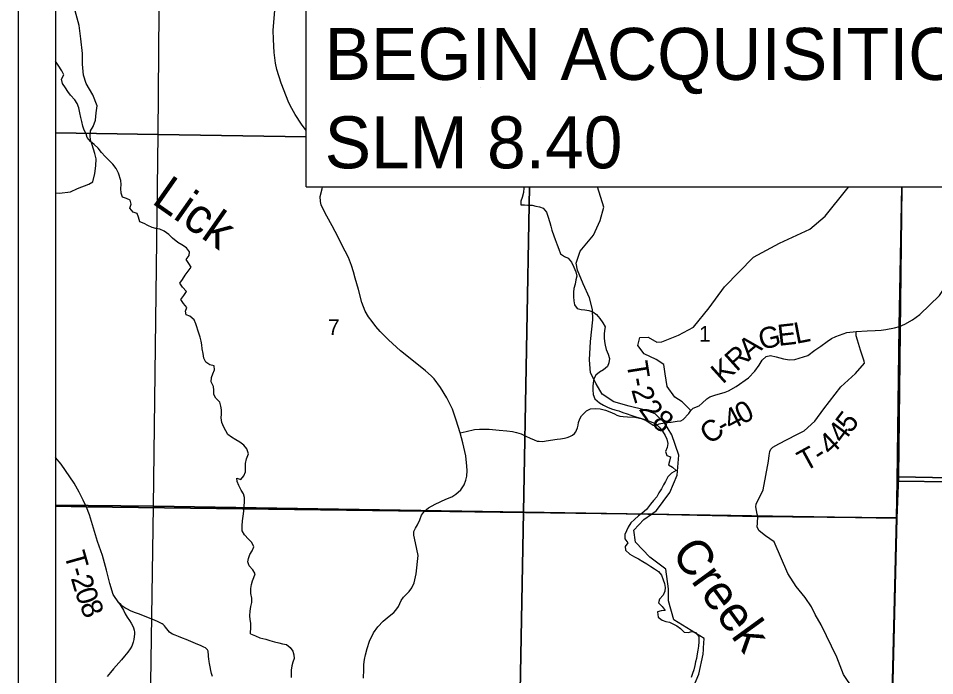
# Model space of a CAD drawing. Extents: x -19 to 40.8, y -1.8 to 26.1.
# Drawn here: x 2 to 4.466, y 15.443 to 17.213 of the extents above; entities that cross this region are included whole.
import ezdxf

# ---------------------------------------------------------------- set-up
doc = ezdxf.new("R2010")
doc.units = 0
for name, color, linetype in [('Default', 7, 'Continuous'), ('GM_X_Corporation', 7, 'Continuous'), ('GM_X_County_Road_Text', 7, 'Continuous'), ('GM_X_Minor_River', 7, 'Continuous'), ('GM_X_Rail_Line', 7, 'Continuous'), ('GM_X_Section', 7, 'Continuous'), ('GM_X_Section_Text', 7, 'Continuous'), ('GM_X_State_Route', 7, 'Continuous'), ('GM_X_Township_Road_Text', 7, 'Continuous'), ('RW_P_Text', 7, 'Continuous'), ('SH_Data', 7, 'Continuous'), ('SH_Text', 7, 'Continuous')]:
    doc.layers.add(name, color=color, linetype=linetype)

msp = doc.modelspace()

# ---------------------------------------------------------------- linework, layer by layer
at = {"layer": 'Default'}
for points in [[(2.1, 17.9061), (2.1, 16.9049), (2.3762, 16.9005), (2.3844, 17.899)], [(2.1, 16.9049), (2.1, 15.9023), (2.3634, 15.8992), (2.3762, 16.9005)], [(2.1, 15.9023), (2.1, 14.6614), (2.3446, 14.653), (2.3634, 15.8992)]]:
    msp.add_lwpolyline(points, close=True, dxfattribs=at)
at = {"layer": 'GM_X_Corporation'}
for points in [[(4.322, 16.3734), (4.3339, 16.3753), (4.3577, 16.3797), (4.3706, 16.3834), (4.3855, 16.3895), (4.4057, 16.4008), (4.4252, 16.4157), (4.4782, 16.4668), (4.5425, 16.5606), (4.5843, 16.6158), (4.5904, 16.6203), (4.6059, 16.6276), (4.6175, 16.6345), (4.6319, 16.6465), (4.6514, 16.663), (4.6648, 16.6758), (4.6846, 16.69), (4.6854, 16.6904)], [(3.1892, 16.0973), (3.2052, 16.1003), (3.2275, 16.1057), (3.2405, 16.1067), (3.2671, 16.1064), (3.2942, 16.1044), (3.3141, 16.1027), (3.3292, 16.1006), (3.3402, 16.098), (3.3534, 16.0938), (3.3655, 16.0884), (3.3772, 16.083), (3.3879, 16.0783), (3.396, 16.0749), (3.4017, 16.0743), (3.4116, 16.0736), (3.4206, 16.075), (3.4501, 16.0803), (3.4589, 16.0812), (3.4697, 16.0823), (3.4768, 16.084), (3.484, 16.0867), (3.4914, 16.0908), (3.4965, 16.0952), (3.4999, 16.1), (3.5017, 16.1041), (3.5042, 16.1105), (3.5059, 16.1173), (3.5074, 16.1249), (3.5105, 16.135), (3.5156, 16.1428), (3.5233, 16.1509), (3.5287, 16.1566), (3.5396, 16.1618), (3.5538, 16.1629), (3.5652, 16.1613), (3.5798, 16.1579), (3.5919, 16.1539), (3.6038, 16.1483), (3.6105, 16.1445), (3.6181, 16.1422), (3.6278, 16.1409), (3.639, 16.14), (3.6587, 16.1395), (3.6754, 16.1357), (3.6891, 16.1303), (3.7085, 16.1175), (3.7152, 16.1166), (3.7246, 16.1209), (3.7386, 16.1236), (3.7566, 16.1261), (3.773, 16.128), (3.7823, 16.1294), (3.789, 16.1324), (3.8043, 16.1493), (3.8096, 16.1568), (3.8156, 16.1631), (3.8317, 16.1695), (3.8399, 16.1769), (3.8529, 16.1885), (3.8604, 16.1936), (3.8766, 16.1993), (3.8928, 16.2034), (3.9018, 16.2063), (3.9112, 16.2103), (3.9318, 16.2221), (3.9647, 16.2453), (3.9817, 16.2631), (3.9934, 16.2791), (4.001, 16.293), (4.0125, 16.3029), (4.0235, 16.3055), (4.0392, 16.3018), (4.0591, 16.2958), (4.0753, 16.2935), (4.0892, 16.2948), (4.1241, 16.3052), (4.1428, 16.3193), (4.1592, 16.3304), (4.1761, 16.3424), (4.1877, 16.3508), (4.2, 16.3566), (4.2288, 16.3667), (4.2544, 16.3699), (4.2838, 16.3713), (4.3054, 16.3724), (4.322, 16.3734)]]:
    msp.add_lwpolyline(points, dxfattribs=at)
at = {"layer": 'GM_X_Rail_Line'}
for points in [[(2.7742, 16.9108), (2.7623, 16.9277), (2.7447, 16.9536), (2.7356, 16.9701), (2.728, 16.9852), (2.7071, 17.038), (2.6958, 17.0752), (2.6919, 17.0924), (2.6882, 17.1209), (2.6864, 17.1555), (2.6861, 17.1808), (2.6885, 17.212), (2.6932, 17.2685), (2.6965, 17.3146), (2.6969, 17.3334)], [(2.844, 16.6542), (2.8301, 16.6799), (2.8206, 16.6987), (2.8148, 16.7112), (2.813, 16.7195), (2.8123, 16.7331), (2.8175, 16.7541), (2.8187, 16.7589)], [(3.1892, 16.0973), (3.1785, 16.131), (3.1679, 16.1604), (3.153, 16.1915), (3.1362, 16.2193), (3.1192, 16.2419), (3.1106, 16.2504), (3.0954, 16.2637), (3.0635, 16.2895), (3.028, 16.3174), (2.9964, 16.3472), (2.9736, 16.3694), (2.962, 16.3836), (2.9518, 16.3964), (2.9421, 16.4096), (2.9332, 16.4248), (2.9244, 16.4476), (2.915, 16.4826), (2.9066, 16.5135), (2.9017, 16.5308), (2.8962, 16.5472), (2.8886, 16.5687), (2.8794, 16.5862), (2.8522, 16.6391), (2.844, 16.6542)], [(2.9285, 15.4367), (2.9292, 15.4595), (2.9299, 15.4732), (2.9315, 15.4867), (2.934, 15.4996), (2.9388, 15.5164), (2.9452, 15.5364), (2.9559, 15.5585), (2.9675, 15.5742), (2.9813, 15.5895), (2.9925, 15.5993), (3.002, 15.6065), (3.0102, 15.6135), (3.0161, 15.6197), (3.0226, 15.6298), (3.03, 15.6452), (3.0365, 15.6544), (3.0514, 15.6695), (3.0588, 15.6792), (3.0652, 15.693), (3.0703, 15.7174), (3.0755, 15.767), (3.0686, 15.8008), (3.0646, 15.8215), (3.0646, 15.8315), (3.0683, 15.8404), (3.0743, 15.8496), (3.0807, 15.8631), (3.0852, 15.8751), (3.0928, 15.8856), (3.1035, 15.8948), (3.1213, 15.9052), (3.1507, 15.9186), (3.1661, 15.9247), (3.1772, 15.9318), (3.1905, 15.9439), (3.1997, 15.9569), (3.2043, 15.9695), (3.2066, 15.9804), (3.2074, 15.9953), (3.2069, 16.0076), (3.2043, 16.0346), (3.1964, 16.0704), (3.1892, 16.0973)]]:
    msp.add_lwpolyline(points, dxfattribs=at)
at = {"layer": 'GM_X_Section'}
msp.add_line((3.243, 17.0276), (3.243, 17.0276), dxfattribs=at)
for points in [[(2.4048, 16.6307), (2.3925, 16.6397), (2.3806, 16.6452), (2.3703, 16.647), (2.36, 16.6502), (2.3489, 16.6554), (2.3385, 16.6606), (2.3271, 16.665), (2.3235, 16.6779), (2.3195, 16.6877), (2.3092, 16.6914), (2.2999, 16.7015), (2.304, 16.713), (2.3012, 16.7236), (2.2908, 16.7276), (2.2801, 16.7313), (2.2766, 16.7419), (2.276, 16.7552), (2.2766, 16.7651), (2.2754, 16.7761), (2.2698, 16.7957), (2.2631, 16.8082), (2.2546, 16.8203), (2.2446, 16.8304), (2.2341, 16.8409), (2.2241, 16.8518), (2.2144, 16.863), (2.204, 16.8732), (2.194, 16.881), (2.1855, 16.8919), (2.1823, 16.9018), (2.1773, 16.9116), (2.1733, 16.9222), (2.1705, 16.9351), (2.1681, 16.9457), (2.1656, 16.9586), (2.1628, 16.9715), (2.1584, 16.9832), (2.1522, 16.9934), (2.1406, 17.0061), (2.1329, 17.0163), (2.127, 17.0261), (2.1189, 17.037), (2.1164, 17.0495), (2.122, 17.0606), (2.1169, 17.0716), (2.1076, 17.0867), (2.1, 17.098)], [(3.3594, 16.7589), (3.3597, 16.7565), (3.3591, 16.7439), (3.3554, 16.7306), (3.3525, 16.7203), (3.3523, 16.7108), (3.3618, 16.7109), (3.3713, 16.7103), (3.3824, 16.7097), (3.3923, 16.7075), (3.4022, 16.7054), (3.4118, 16.7017), (3.4211, 16.6908), (3.425, 16.6806), (3.4298, 16.6628), (3.433, 16.653), (3.4358, 16.6427), (3.4409, 16.6272), (3.4441, 16.6174), (3.4496, 16.6034), (3.454, 16.5917), (3.4591, 16.5792), (3.4691, 16.5713), (3.479, 16.5673), (3.4883, 16.556), (3.495, 16.5428), (3.5001, 16.53), (3.5029, 16.519), (3.4996, 16.5087), (3.4979, 16.4976), (3.495, 16.4854), (3.494, 16.4759), (3.4938, 16.463), (3.4946, 16.4527), (3.4967, 16.4417), (3.5037, 16.4319), (3.5147, 16.4294), (3.5247, 16.4284), (3.5353, 16.4263), (3.546, 16.4223), (3.5557, 16.4155), (3.5645, 16.405), (3.5723, 16.393), (3.5789, 16.3824), (3.5772, 16.3725), (3.5765, 16.3626), (3.5767, 16.3524), (3.5776, 16.3429), (3.5788, 16.3326), (3.582, 16.3213), (3.5871, 16.3088), (3.5904, 16.297), (3.589, 16.2852), (3.5853, 16.2757), (3.5744, 16.2668), (3.5638, 16.2602), (3.5537, 16.2521), (3.5489, 16.2425), (3.5471, 16.2314)], [(2.6251, 15.5557), (2.6256, 15.5746), (2.6255, 15.5849), (2.6238, 15.5944), (2.6229, 15.6043), (2.6239, 15.6168), (2.626, 15.6294), (2.6282, 15.6404), (2.628, 15.6518), (2.6252, 15.664), (2.6254, 15.678), (2.6271, 15.6887), (2.63, 15.6983), (2.6333, 15.7078), (2.637, 15.7174), (2.6308, 15.7283), (2.6215, 15.7388), (2.6172, 15.7494), (2.6193, 15.7589), (2.623, 15.7692), (2.6289, 15.7796), (2.6334, 15.7899), (2.6286, 15.802), (2.619, 15.8106), (2.6082, 15.8223), (2.6027, 15.8332), (2.6022, 15.8465), (2.6035, 15.8598), (2.6049, 15.8724), (2.607, 15.8861), (2.6075, 15.899), (2.6085, 15.9124), (2.6087, 15.9226), (2.6059, 15.9329), (2.5993, 15.943), (2.5935, 15.9551), (2.5888, 15.9657), (2.5875, 15.9752), (2.5986, 15.9715), (2.6068, 15.9815), (2.6112, 15.9922), (2.6114, 16.0048), (2.6113, 16.0143), (2.6142, 16.0269), (2.6197, 16.0406), (2.6146, 16.0535), (2.6072, 16.0633), (2.5961, 16.0719), (2.585, 16.0785), (2.5738, 16.0856), (2.5638, 16.0927), (2.5533, 16.1119), (2.5474, 16.1244), (2.5461, 16.1377), (2.5471, 16.1472), (2.5466, 16.1586), (2.5453, 16.1689), (2.5425, 16.1791), (2.5317, 16.19), (2.5262, 16.1998), (2.5257, 16.2115), (2.5252, 16.2214), (2.5193, 16.2339), (2.5195, 16.246), (2.5232, 16.256), (2.5276, 16.2663), (2.5271, 16.2773), (2.5157, 16.2798), (2.5049, 16.2869), (2.4994, 16.2982), (2.497, 16.3107), (2.4949, 16.3229), (2.4936, 16.3339), (2.4916, 16.3441), (2.4892, 16.3547), (2.486, 16.3653), (2.4773, 16.3903), (2.4729, 16.4013), (2.4618, 16.4114), (2.4518, 16.4143), (2.4498, 16.4245), (2.4538, 16.4348), (2.4442, 16.4454), (2.4372, 16.4563), (2.445, 16.4663), (2.4521, 16.4774), (2.4417, 16.4894), (2.4347, 16.4996), (2.4418, 16.5096), (2.4492, 16.5215), (2.4571, 16.5318), (2.4646, 16.5426), (2.4591, 16.5524), (2.4517, 16.5637), (2.4599, 16.5748), (2.461, 16.5843), (2.4521, 16.5952), (2.4402, 16.6027), (2.4294, 16.6098), (2.4148, 16.6213), (2.4048, 16.6307)], [(3.5471, 16.2314), (3.5461, 16.2219), (3.5455, 16.2124), (3.5468, 16.1999), (3.5515, 16.1885), (3.5638, 16.1777), (3.5749, 16.1714), (3.5849, 16.1662), (3.5956, 16.1618), (3.6051, 16.1592), (3.6158, 16.1564), (3.6262, 16.1519), (3.638, 16.1479), (3.648, 16.1446), (3.6613, 16.1403), (3.6827, 16.1337), (3.6938, 16.1301), (3.7049, 16.126), (3.7145, 16.122), (3.7245, 16.1119), (3.733, 16.101), (3.7408, 16.0901), (3.7451, 16.0795), (3.7472, 16.0681), (3.7462, 16.0578), (3.7417, 16.0463), (3.7449, 16.0357), (3.7552, 16.0325), (3.752, 16.0203), (3.7495, 16.0107), (3.7602, 16.0048), (3.7698, 15.9954), (3.7577, 15.9888), (3.7476, 15.9784), (3.7409, 15.9661), (3.7361, 15.9566), (3.7302, 15.9458), (3.7234, 15.9358), (3.7183, 15.9248), (3.7093, 15.9144), (3.7007, 15.9047), (3.6898, 15.8901), (3.6785, 15.8809), (3.6687, 15.8735), (3.6578, 15.8638), (3.6484, 15.8542), (3.6406, 15.8431), (3.6366, 15.8331), (3.6321, 15.8228), (3.6319, 15.8118), (3.6397, 15.8009), (3.6326, 15.7913), (3.6338, 15.781), (3.6454, 15.7702), (3.6577, 15.7635), (3.6688, 15.7576), (3.6807, 15.7505), (3.6914, 15.7442), (3.7021, 15.7375), (3.7121, 15.7304), (3.7221, 15.7237), (3.7302, 15.7136), (3.7354, 15.7015), (3.7389, 15.6909), (3.7402, 15.6806), (3.7392, 15.6707), (3.7348, 15.6596), (3.725, 15.6489), (3.7225, 15.6393), (3.7325, 15.6296), (3.7407, 15.6187), (3.7293, 15.6177), (3.7194, 15.6153), (3.7215, 15.6005), (3.7319, 15.5927), (3.7418, 15.589), (3.7517, 15.5873), (3.7715, 15.5773)], [(3.7715, 15.5773), (3.7814, 15.5699), (3.7917, 15.5601), (3.802, 15.559), (3.8122, 15.5622), (3.8217, 15.5592), (3.8313, 15.5483), (3.8311, 15.5346), (3.83, 15.5228), (3.8282, 15.5114), (3.8268, 15.5015), (3.8246, 15.4897), (3.8224, 15.4802), (3.8202, 15.4703), (3.8173, 15.4592), (3.8136, 15.4486), (3.8102, 15.4383)], [(2.6251, 15.5557), (2.6384, 15.5505), (2.6502, 15.5449), (2.6662, 15.5412), (2.6765, 15.5382), (2.6891, 15.5345), (2.7005, 15.5316), (2.7104, 15.529), (2.7218, 15.5268), (2.7318, 15.5189), (2.7387, 15.5091), (2.7414, 15.4992), (2.7423, 15.4897), (2.7389, 15.4798), (2.736, 15.4699), (2.7342, 15.4581), (2.7344, 15.4384)]]:
    msp.add_lwpolyline(points, dxfattribs=at)
at = {"layer": 'GM_X_State_Route'}
for points in [[(4.3921, 17.8104), (4.3932, 17.8891), (4.4038, 18.6476), (4.4141, 19.3749), (4.4289, 20.4268), (4.4356, 20.9), (2.1, 20.9), (2.1, 15.8991), (2.1833, 15.8974), (3.0926, 15.8861), (3.7032, 15.8784), (3.9893, 15.872), (4.3628, 15.868), (4.3644, 15.9666), (4.3704, 16.384), (4.3769, 16.7589)], [(2.1, 16.7433), (2.1105, 16.7418), (2.1404, 16.7461), (2.1594, 16.755), (2.1894, 16.7662), (2.2006, 16.7729), (2.2057, 16.7948), (2.2083, 16.8162), (2.2098, 16.835), (2.2062, 16.8493), (2.1986, 16.8722), (2.1945, 16.8849), (2.1935, 16.8976), (2.1944, 16.91), (2.2013, 16.9215), (2.2078, 16.9387), (2.2093, 16.9581), (2.2123, 16.9776), (2.2001, 17.0071), (2.1823, 17.0377), (2.1757, 17.0596), (2.1731, 17.0891), (2.1726, 17.1182), (2.168, 17.1579), (2.1635, 17.194), (2.1533, 17.2333)], [(3.7386, 16.1236), (3.7135, 16.1479), (3.6837, 16.1587), (3.6433, 16.1684), (3.6025, 16.1804), (3.5713, 16.201), (3.5544, 16.2291), (3.5398, 16.2587), (3.5368, 16.2932), (3.5395, 16.3425), (3.5458, 16.4015), (3.5448, 16.4291), (3.5366, 16.4604), (3.5202, 16.4984), (3.5043, 16.5345), (3.5005, 16.5541), (3.5115, 16.5862), (3.5478, 16.6291), (3.5655, 16.6686), (3.5753, 16.7048), (3.5585, 16.7589)], [(3.7401, 16.256), (3.7364, 16.2806), (3.7158, 16.2948), (3.6842, 16.3096), (3.6665, 16.3325), (3.6723, 16.3538), (3.6943, 16.3548), (3.7183, 16.3411), (3.7312, 16.342), (3.7765, 16.3603), (3.8168, 16.3816), (3.8591, 16.4333), (3.9002, 16.4899), (3.9778, 16.5697), (4.0479, 16.6076), (4.1294, 16.6457), (4.1707, 16.6803), (4.2294, 16.7534), (4.2345, 16.7589)], [(4.3769, 16.7589), (4.3704, 16.384), (4.3644, 15.9666), (5.2419, 15.956), (5.3769, 15.9544), (5.3823, 15.9544), (5.3878, 15.9543), (5.57, 15.952), (6.2458, 15.936), (6.5861, 15.9329), (6.6409, 15.9314), (6.7023, 15.9297), (6.805, 15.9268), (6.9672, 15.9223), (6.993, 15.9217), (6.9993, 15.9207), (7.1288, 15.9169)], [(3.9882, 15.8783), (3.9844, 15.8977), (3.9855, 15.9053), (4.0038, 15.9433), (4.0187, 16.0204), (4.0204, 16.0356), (4.0216, 16.0469), (4.0244, 16.0526), (4.0299, 16.0581), (4.0466, 16.0676), (4.0691, 16.0787), (4.0946, 16.0921), (4.1148, 16.1025), (4.1428, 16.1284), (4.167, 16.1616), (4.2128, 16.221), (4.2527, 16.2571), (4.2771, 16.2848), (4.2756, 16.2899), (4.2662, 16.3194), (4.2582, 16.3463), (4.2546, 16.3581), (4.2544, 16.3699)], [(3.8096, 16.1568), (3.7861, 16.1803), (3.7662, 16.1926), (3.746, 16.2218), (3.7401, 16.256)], [(3.8436, 15.5139), (3.8438, 15.518), (3.845, 15.5428), (3.7641, 15.5933), (3.7497, 15.645), (3.749, 15.6765), (3.7422, 15.7302), (3.6994, 15.7626), (3.6603, 15.8027), (3.6562, 15.8349), (3.6829, 15.8632), (3.7034, 15.8778), (3.7168, 15.8874), (3.7526, 15.9364), (3.7724, 15.9831), (3.7769, 16.037), (3.7583, 16.0913), (3.7386, 16.1236)], [(2.27, 15.6389), (2.2554, 15.6618), (2.2461, 15.6913), (2.2373, 15.7269), (2.2261, 15.7667), (2.2133, 15.8046), (2.1916, 15.876), (2.1835, 15.8969), (2.1749, 15.9159), (2.1641, 15.9373), (2.1498, 15.9617), (2.1157, 16.0125), (2.1, 16.0308)], [(7.1288, 15.9169), (6.9993, 15.9207), (6.993, 15.9217), (6.9672, 15.9223), (6.805, 15.9268), (6.7023, 15.9297), (6.6409, 15.9314), (6.5861, 15.9329), (6.2458, 15.936), (5.57, 15.952), (5.3878, 15.9543), (5.3823, 15.9544), (5.3769, 15.9544), (5.2419, 15.956), (4.3644, 15.9666), (4.3628, 15.868), (4.3494, 15.3211)], [(4.3257, 15.3498), (4.3251, 15.3505), (4.2689, 15.3849), (4.2466, 15.4076), (4.2199, 15.4459), (4.2025, 15.4933), (4.1605, 15.58), (4.1444, 15.6081), (4.1337, 15.6283), (4.1173, 15.6538), (4.0927, 15.6836), (4.0704, 15.7184), (4.0341, 15.8035), (4.0106, 15.82), (3.993, 15.8334), (3.9881, 15.843), (3.9886, 15.8546), (3.9895, 15.8715), (3.9882, 15.8783)], [(2.27, 15.6389), (2.2754, 15.6316), (2.2826, 15.6195), (2.2873, 15.6092), (2.2928, 15.6011), (2.2992, 15.5918), (2.3035, 15.5848), (2.3069, 15.5784), (2.3099, 15.5722), (2.3115, 15.5661), (2.3123, 15.5601), (2.3125, 15.5553), (2.3119, 15.5485), (2.311, 15.5404), (2.3093, 15.5336), (2.3073, 15.5276), (2.3053, 15.5228), (2.3011, 15.5157), (2.2943, 15.5067), (2.2853, 15.4955), (2.2776, 15.4859), (2.2563, 15.4612), (2.2483, 15.4516), (2.2389, 15.4412)], [(2.5223, 15.441), (2.5199, 15.4494), (2.5183, 15.4573), (2.5161, 15.4667), (2.514, 15.4757), (2.5131, 15.4815), (2.5124, 15.4889), (2.512, 15.4949), (2.5117, 15.5014), (2.5109, 15.5058), (2.5106, 15.5089), (2.5089, 15.5131), (2.5065, 15.5155), (2.5034, 15.5182), (2.4994, 15.5203), (2.4922, 15.5234), (2.4768, 15.5294), (2.452, 15.5402), (2.4414, 15.5445), (2.4308, 15.5487), (2.4223, 15.5522), (2.415, 15.5549), (2.4104, 15.5575), (2.4069, 15.5604), (2.4033, 15.5645), (2.3994, 15.569), (2.3959, 15.5734), (2.3935, 15.5775), (2.3897, 15.5806), (2.3869, 15.5826), (2.3816, 15.5856), (2.3767, 15.5883), (2.3664, 15.5923), (2.3233, 15.6094), (2.3123, 15.6136), (2.3022, 15.618), (2.2936, 15.6226), (2.2868, 15.6257), (2.2816, 15.6298), (2.2759, 15.6345), (2.27, 15.6389)], [(3.8936, 15.3428), (3.8875, 15.3448), (3.8353, 15.35), (3.8135, 15.4066), (3.8306, 15.4474), (3.843, 15.5014), (3.8436, 15.5139)]]:
    msp.add_lwpolyline(points, dxfattribs=at)
msp.add_lwpolyline([(2.1, 15.8991), (2.1, 14.1), (4.3215, 14.1), (4.3262, 14.3024), (4.3261, 14.4335), (4.3369, 14.8581), (4.3371, 14.8653), (4.3373, 14.8703), (4.3441, 15.1043), (4.3494, 15.3211), (4.3628, 15.868), (3.9893, 15.872), (3.7032, 15.8784), (3.0926, 15.8861), (2.1833, 15.8974)], close=True, dxfattribs=at)
at = {"layer": 'RW_P_Text'}
for points in [[(2.7742, 16.8936), (2.3762, 16.9005), (2.3844, 17.899), (3.3895, 17.8864), (3.3886, 17.8104)], [(4.8227, 16.9645), (5.3277, 16.9579), (5.2973, 15.9612), (5.2848, 15.9609), (4.3678, 15.9788), (4.3772, 16.7589)], [(3.375, 16.7589), (3.3595, 15.883), (2.3634, 15.8992), (2.3762, 16.9005), (2.7742, 16.8936)], [(4.3772, 16.7589), (4.3678, 15.9788), (4.3635, 15.8676), (3.3595, 15.883), (3.375, 16.7589)]]:
    msp.add_lwpolyline(points, dxfattribs=at)
for points in [[(4.3678, 15.9788), (5.2848, 15.9609), (5.2615, 14.8764), (4.3391, 14.8802), (4.3635, 15.8676)], [(2.3634, 15.8992), (3.3595, 15.883), (3.3355, 14.6314), (2.3446, 14.653)], [(3.3595, 15.883), (4.3635, 15.8676), (4.3391, 14.8802), (4.3324, 14.6079), (3.3355, 14.6314)]]:
    msp.add_lwpolyline(points, close=True, dxfattribs=at)
at = {"layer": 'SH_Data'}
for p, q in [((2, 21), (2, 14)), ((2.1, 20.9), (2.1, 14.1))]:
    msp.add_line(p, q, dxfattribs=at)
at = {"layer": 'SH_Text'}
for q in [(2.7742, 17.2367), (4.8076, 16.7589)]:
    msp.add_line((2.7742, 16.7589), q, dxfattribs=at)

# ---------------------------------------------------------------- texts
at = {"layer": 'GM_X_County_Road_Text'}
for s, rotation, p in [('G', 12.8797, (3.9986, 16.3199)), ('E', 6.4377, (4.0457, 16.3308)), ('L', 10.9737, (4.0928, 16.3363)), ('A', 40.1232, (3.9667, 16.2909)), ('R', 41.9739, (3.9324, 16.26)), ('K', 41.9823, (3.8952, 16.2265)), ('0', 27.8832, (3.9472, 16.1182)), ('4', 27.752, (3.9161, 16.1018)), ('C', 36.9035, (3.8604, 16.0636)), ('-', 29.3799, (3.8961, 16.0906))]:
    msp.add_text(s, height=0.0568, rotation=rotation, dxfattribs=at).set_placement(p)
at = {"layer": 'GM_X_Minor_River'}
for s, height, rotation, p in [('Lick', 0.0947, 324.9731, (2.3559, 16.7167)), ('Creek', 0.09468, 305.9828, (3.7546, 15.7723))]:
    msp.add_text(s, height=height, rotation=rotation, dxfattribs=at).set_placement(p)
at = {"layer": 'GM_X_Section_Text'}
for s, p in [('7', (2.8332, 16.3606)), ('1', (3.8315, 16.3426))]:
    msp.add_text(s, height=0.0419, rotation=0, dxfattribs=at).set_placement(p)
at = {"layer": 'GM_X_Township_Road_Text'}
for s, rotation, p in [('T', 279.1023, (3.6362, 16.2855)), ('-', 280.4116, (3.6432, 16.2421)), ('2', 286.2071, (3.6488, 16.2131)), ('2', 305.8587, (3.6679, 16.1604)), ('8', 323.1255, (3.7014, 16.1188)), ('5', 52.7065, (4.2393, 16.0935)), ('4', 52.8517, (4.2182, 16.0656)), ('4', 42.9457, (4.1854, 16.0338)), ('T', 28.6891, (4.1162, 15.9916)), ('-', 33.4929, (4.1579, 16.0146)), ('T', 285.7329, (2.1227, 15.7699)), ('-', 285.8788, (2.1342, 15.7288)), ('2', 286.4628, (2.1408, 15.7058)), ('0', 288.5172, (2.1514, 15.6701)), ('8', 293.0071, (2.1642, 15.6323))]:
    msp.add_text(s, height=0.0568, rotation=rotation, dxfattribs=at).set_placement(p)
at = {"layer": 'SH_Text'}
for s, p in [('BEGIN ACQUISITION', (2.8242, 17.0471)), ('SLM 8.40', (2.8242, 16.8091))]:
    msp.add_text(s, height=0.14, dxfattribs=at).set_placement(p)

doc.saveas('drawing.dxf')
